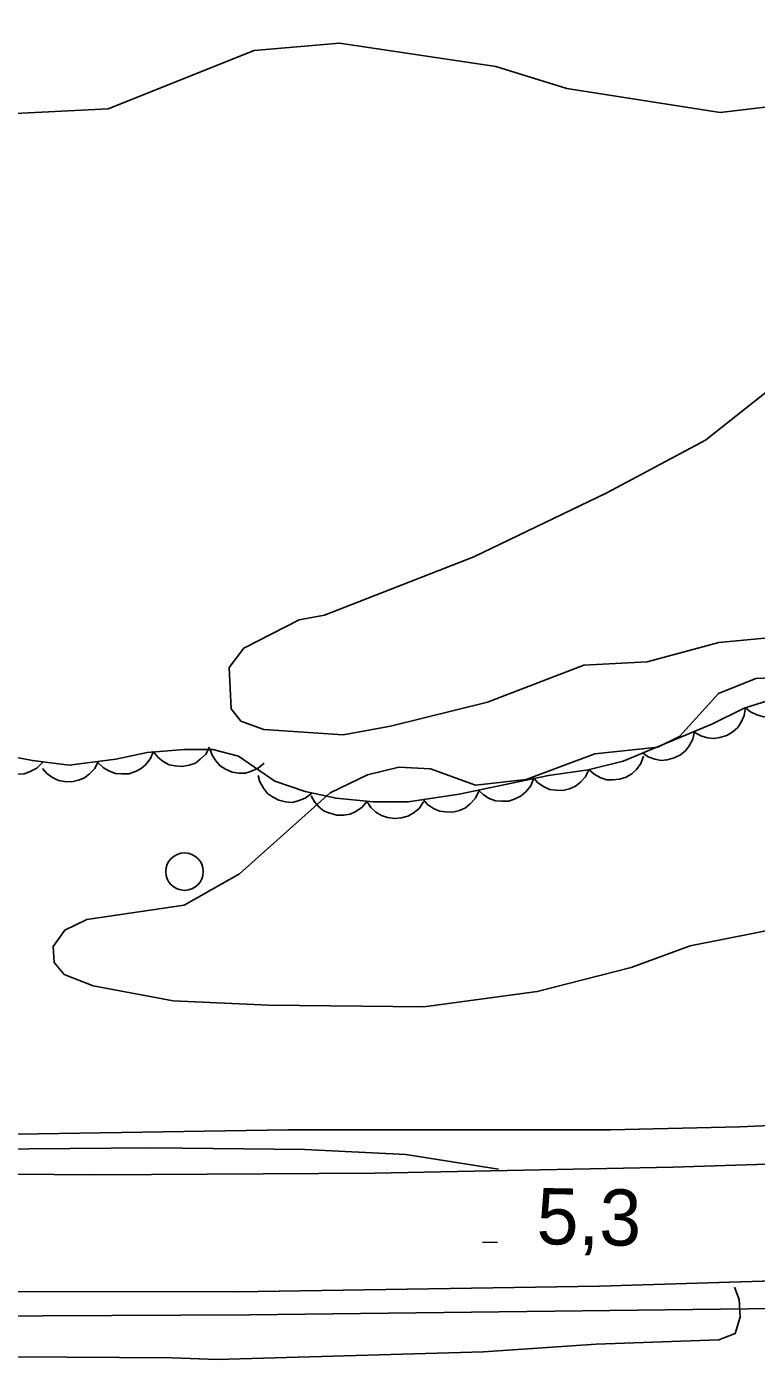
# Model space of a CAD drawing. Extents: x 336540 to 340074, y 5572036 to 5573747.
# Drawn here: x 337139.3 to 337178.3, y 5572550.4 to 5572621.6 of the extents above; entities that cross this region are included whole.
import ezdxf

# ---------------------------------------------------------------- set-up
doc = ezdxf.new("R2010")
doc.units = 0
for name, color, linetype in [('Niveau 1', 7, 'Continuous'), ('Niveau 2', 7, 'Continuous'), ('Niveau 21', 7, 'Continuous'), ('Niveau 3', 7, 'Continuous'), ('Niveau 36', 7, 'Continuous'), ('Niveau 44', 7, 'Continuous')]:
    doc.layers.add(name, color=color, linetype=linetype)

msp = doc.modelspace()

# ---------------------------------------------------------------- linework, layer by layer
at = {"layer": 'Niveau 1'}
for points in [[(337190.83, 5572575.69), (337174.75, 5572572.49), (337171.59, 5572571.34), (337166.58, 5572570.05), (337160.53, 5572569.23), (337152.24, 5572569.32), (337147.15, 5572569.56), (337142.88, 5572570.36), (337141.33, 5572570.97), (337140.79, 5572571.6), (337140.74, 5572572.46), (337141.36, 5572573.34), (337142.54, 5572573.9), (337147.73, 5572574.67), (337150.69, 5572576.34), (337155.53, 5572580.67), (337157.52, 5572581.63), (337159.2, 5572582.04), (337160.89, 5572581.95), (337163.29, 5572581.08), (337165.99, 5572581.38), (337169.65, 5572582.75), (337173.02, 5572583.1), (337174.18, 5572583.67), (337176.26, 5572585.98), (337178.25, 5572586.77), (337180.27, 5572586.87)], [(337135.12, 5572561.61), (337145.99, 5572561.71), (337154.17, 5572561.62), (337159.56, 5572561.36), (337164.51, 5572560.57)], [(337177.11, 5572554.26), (337177.36, 5572553.6), (337177.42, 5572552.66), (337177.14, 5572551.79), (337176.27, 5572551.45), (337169.72, 5572551.22), (337163.71, 5572550.82), (337149.49, 5572550.41), (337147.1, 5572550.49), (337133.01, 5572550.58), (337127.35, 5572550.47), (337115.64, 5572550.52), (337104.22, 5572550.84), (337087.28, 5572551.97)]]:
    msp.add_lwpolyline(points, dxfattribs=at)
at = {"layer": 'Niveau 2'}
for points in [[(337181.57, 5572617.63), (337176.35, 5572617.01), (337168.16, 5572618.29), (337164.37, 5572619.46), (337156.03, 5572620.71), (337151.47, 5572620.32), (337143.67, 5572617.21), (337137.62, 5572616.9), (337128.47, 5572616.93), (337124.42, 5572616.56), (337119.78, 5572614.81), (337116.94, 5572614.32), (337114.69, 5572615.22), (337113.09, 5572616.48), (337112.34, 5572617.81), (337112.2, 5572620.69), (337111.63, 5572622.02)], [(337179.47, 5572589.01), (337176.28, 5572588.7), (337172.45, 5572587.66), (337169.07, 5572587.48), (337163.93, 5572585.51), (337158.75, 5572584.23), (337156.22, 5572583.77), (337151.98, 5572584.05), (337150.76, 5572584.49), (337150.24, 5572585.15), (337150.13, 5572587.36), (337150.91, 5572588.4), (337153.88, 5572589.91), (337155.23, 5572590.15), (337163.19, 5572593.27), (337170.3, 5572596.69), (337175.56, 5572599.51), (337180.59, 5572603.5)]]:
    msp.add_lwpolyline(points, dxfattribs=at)
at = {"layer": 'Niveau 21'}
for points in [[(337067.1, 5572566.52), (337092.27, 5572564.2), (337096.55, 5572563.84), (337101.41, 5572563.55), (337117.29, 5572563.1), (337129.99, 5572562.58), (337136.6, 5572562.4), (337153.26, 5572562.66), (337170.49, 5572562.67), (337177.39, 5572562.83), (337181.83, 5572563.02), (337202.37, 5572564.24), (337213.14, 5572564.75), (337219.59, 5572565.17), (337255.85, 5572568.43), (337280.4, 5572570.85), (337289.47, 5572571.86), (337370.68, 5572582.43), (337393.64, 5572585.48), (337410.56, 5572587.83), (337420.85, 5572589.04), (337469.47, 5572594.26)], [(337475.89, 5572592.36), (337426.83, 5572587.03), (337409.93, 5572585.09), (337387.78, 5572582.21), (337292.3, 5572570.26), (337250.14, 5572565.61), (337233.14, 5572564.02), (337216.87, 5572562.87), (337197.38, 5572561.67), (337181.62, 5572560.93), (337173.83, 5572560.67), (337157.89, 5572560.36), (337143.02, 5572560.27), (337136.29, 5572560.31), (337124.2, 5572560.58), (337111.04, 5572561.06), (337095.79, 5572561.86), (337085.79, 5572562.64)], [(337073.99, 5572555.28), (337110.67, 5572552.6), (337151.23, 5572552.78), (337188.2, 5572553.24), (337232.65, 5572555.84), (337279.67, 5572560.35), (337323.44, 5572565.76), (337344.89, 5572568.84), (337348.4, 5572569.26), (337352.81, 5572569.65), (337362.62, 5572571.35), (337367.63, 5572572.04), (337373.89, 5572572.71), (337392.31, 5572574.42), (337443.52, 5572580.72), (337457.51, 5572582.4)], [(337352.94, 5572571.52), (337305.72, 5572565.51), (337279.5, 5572562.41), (337244.11, 5572558.62), (337235.32, 5572557.79), (337223.99, 5572556.9), (337216.56, 5572556.58), (337194.91, 5572555.24), (337184.99, 5572554.79), (337169.91, 5572554.32), (337150.52, 5572554.01), (337133.92, 5572554.03), (337117.83, 5572554.35), (337100.64, 5572555), (337088.68, 5572555.77)]]:
    msp.add_lwpolyline(points, dxfattribs=at)
at = {"layer": 'Niveau 3'}
msp.add_line((337163.65, 5572556.67), (337164.45, 5572556.65), dxfattribs=at)
at = {"layer": 'Niveau 36'}
msp.add_circle((337147.749, 5572576.461), 1, dxfattribs=at)
at = {"layer": 'Niveau 44'}
for points in [[(337179.55, 5572585.8), (337177.63, 5572585.19), (337175.9, 5572584.34), (337171.16, 5572582.36), (337169.29, 5572581.9), (337167.18, 5572581.59), (337162.41, 5572580.6), (337159.69, 5572580.19), (337157.82, 5572580.19), (337155.84, 5572580.38), (337154.2, 5572580.74), (337152.58, 5572581.29), (337150.63, 5572582.62), (337149.26, 5572582.98), (337147.74, 5572582.99), (337145.76, 5572582.82), (337144.08, 5572582.46), (337141.59, 5572582.15), (337139.63, 5572582.39), (337137.21, 5572582.85)], [(337180.55, 5572586.12), (337180.43, 5572585.72), (337180.21, 5572585.38), (337179.99, 5572585.13), (337179.7, 5572584.94), (337179.35, 5572584.8), (337178.97, 5572584.74), (337178.65, 5572584.73), (337178.31, 5572584.83), (337177.97, 5572584.99), (337177.69, 5572585.21)], [(337177.69, 5572585.22), (337177.63, 5572584.8), (337177.46, 5572584.44), (337177.28, 5572584.16), (337177.02, 5572583.93), (337176.7, 5572583.74), (337176.33, 5572583.63), (337176.01, 5572583.57), (337175.66, 5572583.61), (337175.31, 5572583.72), (337175, 5572583.9)], [(337174.97, 5572583.95), (337174.89, 5572583.54), (337174.69, 5572583.18), (337174.5, 5572582.92), (337174.22, 5572582.7), (337173.89, 5572582.53), (337173.52, 5572582.44), (337173.2, 5572582.4), (337172.85, 5572582.47), (337172.5, 5572582.6), (337172.2, 5572582.8)], [(337140.17, 5572582.29), (337139.87, 5572581.99), (337139.51, 5572581.8), (337139.2, 5572581.68), (337138.85, 5572581.66), (337138.48, 5572581.7), (337138.13, 5572581.83), (337137.83, 5572581.97), (337137.58, 5572582.22), (337137.36, 5572582.52), (337137.22, 5572582.85)], [(337146.1, 5572582.89), (337145.94, 5572582.5), (337145.68, 5572582.19), (337145.44, 5572581.96), (337145.13, 5572581.8), (337144.78, 5572581.69), (337144.39, 5572581.68), (337144.07, 5572581.7), (337143.74, 5572581.82), (337143.42, 5572582.01), (337143.16, 5572582.26)], [(337149.09, 5572583.11), (337148.89, 5572582.74), (337148.59, 5572582.46), (337148.33, 5572582.26), (337148, 5572582.14), (337147.63, 5572582.08), (337147.25, 5572582.11), (337146.93, 5572582.17), (337146.62, 5572582.34), (337146.33, 5572582.57), (337146.1, 5572582.85)], [(337152, 5572582.26), (337151.69, 5572581.98), (337151.32, 5572581.82), (337151, 5572581.72), (337150.65, 5572581.72), (337150.29, 5572581.78), (337149.94, 5572581.94), (337149.65, 5572582.11), (337149.42, 5572582.37), (337149.22, 5572582.68), (337149.1, 5572583.02)], [(337143.15, 5572582.34), (337142.96, 5572581.97), (337142.68, 5572581.68), (337142.42, 5572581.47), (337142.09, 5572581.34), (337141.73, 5572581.26), (337141.35, 5572581.28), (337141.03, 5572581.33), (337140.71, 5572581.49), (337140.41, 5572581.7), (337140.17, 5572581.97)], [(337172.26, 5572582.63), (337172.11, 5572582.24), (337171.87, 5572581.91), (337171.63, 5572581.68), (337171.32, 5572581.51), (337170.97, 5572581.39), (337170.59, 5572581.36), (337170.27, 5572581.37), (337169.93, 5572581.49), (337169.61, 5572581.67), (337169.34, 5572581.91)], [(337154.53, 5572580.63), (337154.2, 5572580.38), (337153.81, 5572580.24), (337153.49, 5572580.16), (337153.14, 5572580.19), (337152.78, 5572580.27), (337152.45, 5572580.46), (337152.18, 5572580.64), (337151.96, 5572580.92), (337151.78, 5572581.25), (337151.69, 5572581.59)], [(337166.38, 5572581.42), (337166.23, 5572581.04), (337165.97, 5572580.72), (337165.73, 5572580.5), (337165.41, 5572580.34), (337165.06, 5572580.23), (337164.68, 5572580.22), (337164.35, 5572580.24), (337164.02, 5572580.37), (337163.71, 5572580.56), (337163.45, 5572580.82)], [(337169.34, 5572581.91), (337169.16, 5572581.53), (337168.89, 5572581.23), (337168.63, 5572581.02), (337168.31, 5572580.88), (337167.95, 5572580.8), (337167.57, 5572580.81), (337167.24, 5572580.85), (337166.92, 5572581), (337166.62, 5572581.21), (337166.38, 5572581.47)], [(337163.46, 5572580.76), (337163.28, 5572580.38), (337163, 5572580.08), (337162.75, 5572579.87), (337162.43, 5572579.73), (337162.07, 5572579.64), (337161.68, 5572579.65), (337161.36, 5572579.69), (337161.04, 5572579.84), (337160.73, 5572580.05), (337160.49, 5572580.31)], [(337157.5, 5572580.22), (337157.23, 5572579.9), (337156.9, 5572579.67), (337156.6, 5572579.53), (337156.25, 5572579.47), (337155.88, 5572579.48), (337155.51, 5572579.58), (337155.21, 5572579.69), (337154.93, 5572579.91), (337154.69, 5572580.19), (337154.51, 5572580.51)], [(337160.5, 5572580.19), (337160.27, 5572579.84), (337159.95, 5572579.59), (337159.67, 5572579.42), (337159.33, 5572579.33), (337158.96, 5572579.29), (337158.58, 5572579.36), (337158.27, 5572579.45), (337157.97, 5572579.64), (337157.7, 5572579.89), (337157.5, 5572580.19)]]:
    msp.add_lwpolyline(points, dxfattribs=at)

# ---------------------------------------------------------------- texts
at = {"layer": 'Niveau 3'}
msp.add_text('5,3    ', height=2.9999, rotation=358.93393, dxfattribs=at).set_placement((337166.53, 5572556.57))

doc.saveas('drawing.dxf')
